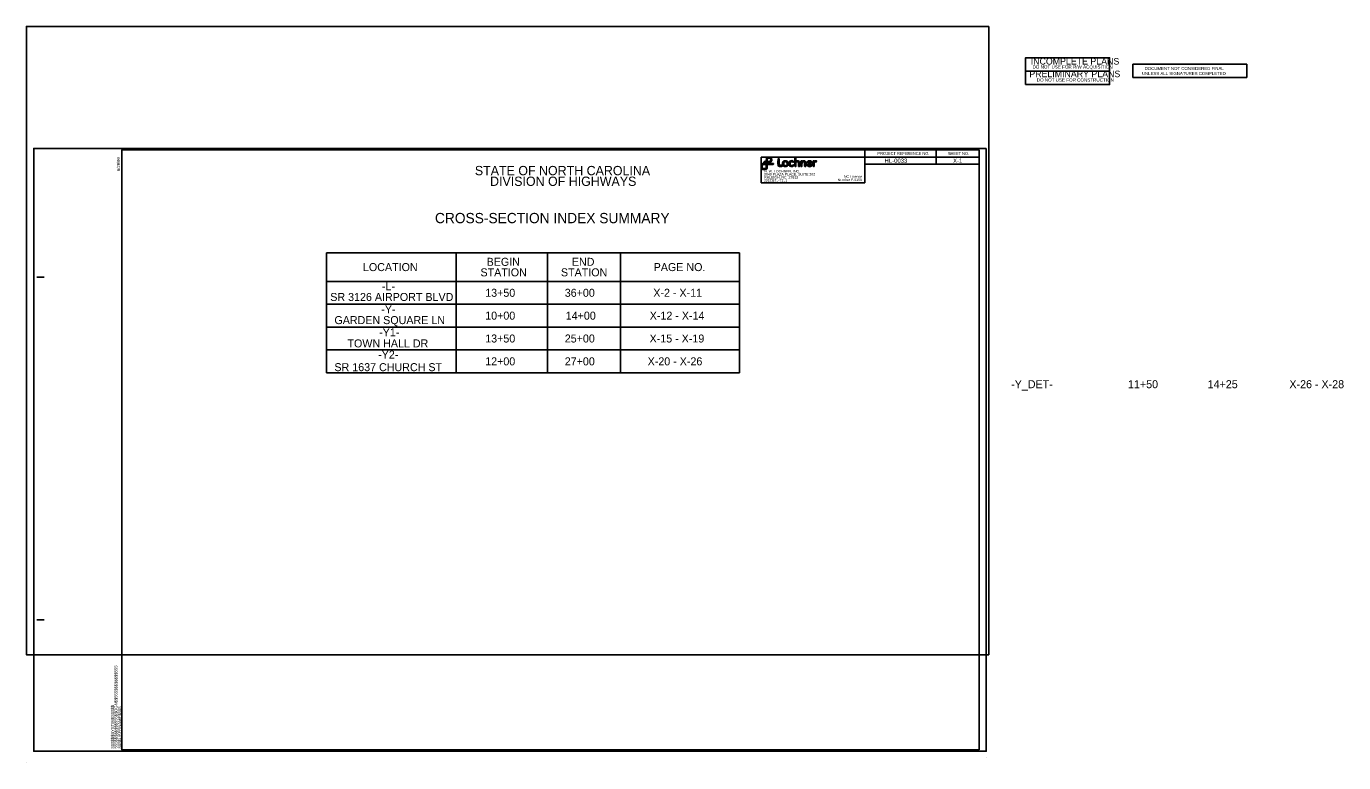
# Model space of a CAD drawing. Extents: x 1385764 to 1388069, y 199675 to 203361.
import ezdxf

# ---------------------------------------------------------------- set-up
doc = ezdxf.new("R2010")
doc.units = 0
for name, color, linetype in [('Old_Level_61', 7, 'Continuous'), ('Old_Level_62', 7, 'Continuous'), ('Prop XSC Text', 7, 'Continuous'), ('Sheet Data Field CELL', 7, 'Continuous'), ('Sheet Plan CELL', 7, 'Continuous'), ('Sheet Plot Border Inside CELL', 7, 'Continuous'), ('Sheet Plot Border Outside CELL', 7, 'Continuous'), ('Sheet Sticker Exception Certification CELL', 7, 'Continuous'), ('Sheet Sticker Incomplete CELL', 7, 'Continuous'), ('Sheet Sticker Preliminary CELL', 7, 'Continuous'), ('Sheet Summary CELL', 7, 'Continuous'), ('Sheet Summary Earthwork CELL', 7, 'Continuous')]:
    doc.layers.add(name, color=color, linetype=linetype)

msp = doc.modelspace()

# ---------------------------------------------------------------- linework, layer by layer
at = {"layer": 'Old_Level_61'}
for p, q in [((1387443.5, 203147.4), (1387443.5, 203147.4)), ((1385777.5, 202092.4), (1385777.5, 202092.4))]:
    msp.add_line(p, q, dxfattribs=at)
at = {"layer": 'Old_Level_62'}
for p, q in [((1387448, 203167.4), (1387448, 203167.4)), ((1385764.5, 202072.4), (1385764.5, 202072.4))]:
    msp.add_line(p, q, dxfattribs=at)
at = {"layer": 'Prop XSC Text'}
for p, q in [((1387049.6, 203132.3), (1387049.6, 203087.4)), ((1387230.9, 203132.3), (1387049.6, 203132.3)), ((1387230.9, 203132.3), (1387230.9, 203087.4)), ((1387230.9, 203087.4), (1387049.6, 203087.4)), ((1386288.9, 202964.8), (1387011.9, 202964.8)), ((1386288.9, 202964.8), (1386288.9, 202754.8)), ((1386516, 202964.8), (1386516, 202754.8)), ((1386676, 202964.8), (1386676, 202754.8)), ((1386803.7, 202964.8), (1386803.7, 202754.8)), ((1387011.9, 202964.8), (1387011.9, 202754.8)), ((1386288.9, 202914.8), (1387011.9, 202914.8)), ((1386288.9, 202874.8), (1387011.9, 202874.8)), ((1386288.9, 202834.8), (1387011.9, 202834.8)), ((1386288.9, 202794.8), (1387011.9, 202794.8)), ((1386288.9, 202754.8), (1387011.9, 202754.8))]:
    msp.add_line(p, q, dxfattribs=at)
for points in [[(1387058.6, 203121.3), (1387058.5, 203121.3), (1387058.4, 203121.3), (1387058.3, 203121.3), (1387057.2, 203121.3), (1387056.1, 203121.3), (1387055, 203121.3), (1387054.7, 203121.3), (1387054.3, 203121.2), (1387053.9, 203121.2), (1387051.1, 203120.7), (1387049.1, 203117.8), (1387049.6, 203115), (1387050.2, 203112.1), (1387052.7, 203110.2), (1387055.7, 203110.5), (1387058.3, 203110.8), (1387060.4, 203113.2), (1387060.4, 203115.8), (1387060.4, 203119.7), (1387060.4, 203123.6), (1387060.4, 203127.6), (1387060.4, 203129.5), (1387062.2, 203130.9), (1387064, 203130.4), (1387065.4, 203130.1), (1387066.4, 203128.8), (1387066.3, 203127.3), (1387066.1, 203125.9), (1387064.9, 203124.7), (1387063.4, 203124.6), (1387062.8, 203124.6), (1387062.2, 203124.6), (1387061.5, 203124.6), (1387061.4, 203124.6), (1387061.3, 203124.6), (1387061.2, 203124.6), (1387061.3, 203124), (1387061.4, 203123.5), (1387061.7, 203123), (1387061.8, 203123), (1387061.9, 203122.9), (1387062, 203122.9), (1387062.6, 203122.9), (1387063.2, 203122.9), (1387063.9, 203123), (1387066.5, 203123.2), (1387068.5, 203125.8), (1387067.9, 203128.6), (1387067.3, 203131.1), (1387065, 203132.6), (1387062.5, 203132.2), (1387060.5, 203131.9), (1387058.8, 203130), (1387058.7, 203128), (1387058.6, 203127), (1387058.6, 203126), (1387058.6, 203125), (1387058.6, 203124.9), (1387058.6, 203124.8), (1387058.6, 203124.6), (1387058.5, 203124.6), (1387058.4, 203124.6), (1387058.3, 203124.6), (1387057.6, 203124.6), (1387056.9, 203124.6), (1387056.2, 203124.6), (1387055.4, 203124.6), (1387054.8, 203124.2), (1387054.6, 203123.4), (1387054.5, 203123.3), (1387054.5, 203123.1), (1387054.5, 203122.9), (1387055.9, 203122.9), (1387057.3, 203122.9), (1387058.6, 203122.9), (1387058.6, 203122.3), (1387058.6, 203121.8), (1387058.6, 203121.3)], [(1387081.3, 203118.1), (1387081.3, 203122), (1387081.3, 203125.8), (1387081.3, 203129.6), (1387080.5, 203129.6), (1387079.8, 203129.6), (1387079.1, 203129.6), (1387079.1, 203125.1), (1387079.1, 203120.6), (1387079.1, 203116.1), (1387081.6, 203116.1), (1387084.1, 203116.1), (1387086.6, 203116.1), (1387086.6, 203116.7), (1387086.6, 203117.2), (1387086.6, 203117.8), (1387086.7, 203118), (1387086.6, 203118.1), (1387086.4, 203118.1), (1387084.8, 203118.1), (1387083.2, 203118.1), (1387081.6, 203118.1), (1387081.5, 203118.1), (1387081.4, 203118.1), (1387081.3, 203118.1)], [(1387115, 203116.1), (1387115.7, 203116.1), (1387116.4, 203116.1), (1387117, 203116.1), (1387117, 203116.2), (1387117.1, 203116.2), (1387117.1, 203116.3), (1387117.1, 203118.1), (1387117.1, 203120), (1387117, 203121.8), (1387117, 203122.2), (1387117, 203122.6), (1387116.9, 203123), (1387116.7, 203124.4), (1387115.9, 203125.4), (1387114.5, 203125.8), (1387113, 203126.2), (1387111.6, 203125.8), (1387110.6, 203124.6), (1387110.6, 203124.6), (1387110.5, 203124.5), (1387110.4, 203124.4), (1387110.4, 203124.6), (1387110.4, 203124.7), (1387110.4, 203124.8), (1387110.4, 203126.3), (1387110.4, 203127.9), (1387110.4, 203129.5), (1387110.4, 203129.7), (1387110.4, 203129.9), (1387110.3, 203130.1), (1387110, 203130.9), (1387109.1, 203131.4), (1387108.4, 203131.3), (1387108.4, 203126.2), (1387108.4, 203121.2), (1387108.4, 203116.1), (1387109, 203116.1), (1387109.7, 203116.1), (1387110.4, 203116.1), (1387110.4, 203116.2), (1387110.4, 203116.3), (1387110.4, 203116.4), (1387110.4, 203117.9), (1387110.4, 203119.4), (1387110.4, 203120.9), (1387110.4, 203121.2), (1387110.4, 203121.6), (1387110.5, 203122), (1387110.7, 203123.2), (1387111.5, 203123.9), (1387112.7, 203124.1), (1387113.8, 203124.2), (1387114.7, 203123.7), (1387114.9, 203122.5), (1387114.9, 203122.3), (1387115, 203122), (1387115, 203121.7), (1387115, 203120.6), (1387115, 203119.5), (1387115, 203118.3), (1387115, 203117.6), (1387115, 203116.9), (1387115, 203116.1)], [(1387058.6, 203119.5), (1387058.5, 203119.5), (1387058.4, 203119.5), (1387058.4, 203119.5), (1387057.2, 203119.5), (1387056.1, 203119.5), (1387054.9, 203119.5), (1387054.7, 203119.5), (1387054.5, 203119.5), (1387054.2, 203119.5), (1387052.3, 203119.1), (1387051, 203117.1), (1387051.3, 203115.2), (1387051.7, 203113.4), (1387053.2, 203112.2), (1387055.1, 203112.2), (1387056.9, 203112.3), (1387058.5, 203113.8), (1387058.6, 203115.6), (1387058.7, 203116.9), (1387058.6, 203118.1), (1387058.6, 203119.4), (1387058.6, 203119.4), (1387058.6, 203119.5), (1387058.6, 203119.5)], [(1387058.6, 203119.5), (1387058.6, 203119.5), (1387058.6, 203119.4), (1387058.6, 203119.4), (1387058.6, 203118.1), (1387058.7, 203116.9), (1387058.6, 203115.6), (1387058.5, 203113.8), (1387056.9, 203112.3), (1387055.1, 203112.2), (1387053.2, 203112.2), (1387051.7, 203113.4), (1387051.3, 203115.2), (1387051, 203117.1), (1387052.3, 203119.1), (1387054.2, 203119.5), (1387054.5, 203119.5), (1387054.7, 203119.5), (1387054.9, 203119.5), (1387056.1, 203119.5), (1387057.2, 203119.5), (1387058.4, 203119.5), (1387058.4, 203119.5), (1387058.5, 203119.5), (1387058.6, 203119.5)], [(1387058.6, 203119.5), (1387058.6, 203119.5), (1387058.6, 203119.4), (1387058.6, 203119.4), (1387058.6, 203118.1), (1387058.7, 203116.9), (1387058.6, 203115.6), (1387058.5, 203113.8), (1387056.9, 203112.3), (1387055.1, 203112.2), (1387053.2, 203112.2), (1387051.7, 203113.4), (1387051.3, 203115.2), (1387051, 203117.1), (1387052.3, 203119.1), (1387054.2, 203119.5), (1387054.5, 203119.5), (1387054.7, 203119.5), (1387054.9, 203119.5), (1387056.1, 203119.5), (1387057.2, 203119.5), (1387058.4, 203119.5), (1387058.4, 203119.5), (1387058.5, 203119.5), (1387058.6, 203119.5)], [(1387061.2, 203121.3), (1387061.3, 203120.7), (1387061.4, 203120.1), (1387061.8, 203119.7), (1387061.8, 203119.6), (1387062, 203119.5), (1387062.1, 203119.5), (1387064.7, 203119.5), (1387067.3, 203119.5), (1387069.9, 203119.5), (1387070.8, 203119.5), (1387071.6, 203120.4), (1387071.5, 203121.3), (1387068.1, 203121.3), (1387064.7, 203121.3), (1387061.2, 203121.3)], [(1387097.1, 203120.9), (1387097.1, 203123.8), (1387094.9, 203125.9), (1387092, 203125.9), (1387089.2, 203125.9), (1387087, 203123.8), (1387087, 203120.9), (1387087, 203118), (1387089.2, 203115.8), (1387092, 203115.8), (1387094.9, 203115.8), (1387097.1, 203118), (1387097.1, 203120.9)], [(1387089.1, 203120.7), (1387089.1, 203122), (1387089.5, 203122.9), (1387090.4, 203123.6), (1387091.8, 203124.6), (1387094.3, 203124.1), (1387094.9, 203121.8), (1387095.2, 203120.5), (1387095, 203119.4), (1387094, 203118.5), (1387092.4, 203116.9), (1387089.7, 203117.8), (1387089.2, 203120), (1387089.1, 203120.3), (1387089.1, 203120.6), (1387089.1, 203120.7)], [(1387106.9, 203124.2), (1387105.8, 203125.8), (1387103.5, 203126.4), (1387101.3, 203125.6), (1387099.2, 203124.9), (1387097.9, 203122.9), (1387098.1, 203120.5), (1387098.2, 203118.3), (1387099.7, 203116.5), (1387101.7, 203116), (1387103.9, 203115.5), (1387106, 203116.1), (1387107, 203117.6), (1387106.6, 203118), (1387106.2, 203118.5), (1387105.8, 203118.9), (1387105.6, 203118.8), (1387105.5, 203118.6), (1387105.3, 203118.5), (1387104.1, 203117.3), (1387101.9, 203117.4), (1387100.8, 203118.8), (1387100.3, 203119.5), (1387100.1, 203120.3), (1387100.2, 203121.2), (1387100.3, 203122.4), (1387101.1, 203123.5), (1387102.2, 203123.9), (1387103.4, 203124.3), (1387104.7, 203124), (1387105.5, 203123), (1387105.5, 203123), (1387105.6, 203122.9), (1387105.6, 203122.8), (1387106.1, 203123.3), (1387106.5, 203123.8), (1387106.9, 203124.2)], [(1387119.1, 203116.1), (1387119.8, 203116.1), (1387120.4, 203116.1), (1387121.1, 203116.1), (1387121.1, 203116.2), (1387121.1, 203116.3), (1387121.1, 203116.4), (1387121.1, 203117.9), (1387121.1, 203119.5), (1387121.1, 203121), (1387121.1, 203121.3), (1387121.2, 203121.6), (1387121.2, 203121.9), (1387121.4, 203123.1), (1387122.2, 203123.9), (1387123.4, 203124.1), (1387124.5, 203124.2), (1387125.4, 203123.8), (1387125.6, 203122.6), (1387125.7, 203122.3), (1387125.7, 203122.1), (1387125.7, 203121.8), (1387125.7, 203120), (1387125.7, 203118.2), (1387125.7, 203116.4), (1387125.7, 203116.3), (1387125.7, 203116.2), (1387125.7, 203116.1), (1387126.4, 203116.1), (1387127.1, 203116.1), (1387127.8, 203116.1), (1387127.8, 203116.2), (1387127.8, 203116.3), (1387127.8, 203116.4), (1387127.8, 203118.1), (1387127.8, 203119.8), (1387127.8, 203121.5), (1387127.8, 203121.9), (1387127.8, 203122.3), (1387127.7, 203122.6), (1387127.6, 203123.7), (1387127.2, 203124.6), (1387126.4, 203125.2), (1387125.8, 203125.7), (1387125.1, 203125.9), (1387124.4, 203125.9), (1387123.1, 203126), (1387122, 203125.6), (1387121.2, 203124.6), (1387121.2, 203124.5), (1387121.1, 203124.5), (1387121.1, 203124.4), (1387121.1, 203124.9), (1387121.1, 203125.2), (1387121.1, 203125.6), (1387120.4, 203125.6), (1387119.7, 203125.6), (1387119.1, 203125.6), (1387119.1, 203122.5), (1387119.1, 203119.3), (1387119.1, 203116.1)], [(1387138.8, 203120.2), (1387138.8, 203120.5), (1387138.8, 203120.8), (1387138.8, 203121.2), (1387138.7, 203122.1), (1387138.5, 203123), (1387138, 203123.8), (1387137, 203125.4), (1387135.5, 203126), (1387133.7, 203125.9), (1387131.7, 203125.8), (1387130.4, 203124.7), (1387129.7, 203122.9), (1387129.2, 203121.6), (1387129.2, 203120.3), (1387129.6, 203119), (1387129.9, 203118.1), (1387130.5, 203117.4), (1387131.3, 203116.8), (1387133, 203115.5), (1387135.9, 203115.5), (1387137.7, 203116.8), (1387138, 203117.1), (1387138.3, 203117.4), (1387138.6, 203117.6), (1387138.2, 203118.1), (1387137.8, 203118.5), (1387137.4, 203118.9), (1387137.3, 203118.9), (1387137.2, 203118.8), (1387137.2, 203118.7), (1387136.3, 203118), (1387135.3, 203117.6), (1387134.2, 203117.7), (1387133.2, 203117.8), (1387132.4, 203118.1), (1387131.9, 203118.9), (1387131.6, 203119.3), (1387131.5, 203119.7), (1387131.5, 203120.2), (1387132.7, 203120.2), (1387133.9, 203120.2), (1387135.1, 203120.2), (1387136.3, 203120.2), (1387137.5, 203120.2), (1387138.8, 203120.2)], [(1387136.6, 203121.9), (1387134.9, 203121.9), (1387133.2, 203121.9), (1387131.5, 203121.9), (1387131.4, 203122.8), (1387132.6, 203124), (1387133.8, 203124), (1387135.4, 203124.2), (1387136.6, 203123.2), (1387136.6, 203121.9)], [(1387146.5, 203125.5), (1387146.5, 203125.5), (1387146.5, 203125.6), (1387146.5, 203125.6), (1387146.4, 203125.6), (1387146.4, 203125.6), (1387146.3, 203125.6), (1387144.8, 203126), (1387143.5, 203125.7), (1387142.4, 203124.5), (1387142.4, 203124.5), (1387142.4, 203124.5), (1387142.3, 203124.4), (1387142.3, 203124.9), (1387142.3, 203125.3), (1387142.3, 203125.6), (1387141.6, 203125.6), (1387141, 203125.6), (1387140.4, 203125.6), (1387140.4, 203122.4), (1387140.4, 203119.3), (1387140.4, 203116.1), (1387141.1, 203116.1), (1387141.7, 203116.1), (1387142.4, 203116.1), (1387142.4, 203116.2), (1387142.4, 203116.3), (1387142.4, 203116.4), (1387142.4, 203118), (1387142.4, 203119.7), (1387142.4, 203121.3), (1387142.5, 203122.6), (1387143.3, 203123.6), (1387144.6, 203123.8), (1387145.1, 203123.9), (1387145.5, 203123.8), (1387146, 203123.6), (1387146, 203123.7), (1387146, 203123.8), (1387146.1, 203123.9), (1387146.2, 203124.4), (1387146.3, 203125), (1387146.5, 203125.5)]]:
    msp.add_open_spline(points, degree=3, dxfattribs=at)
at = {"layer": 'Sheet Plan CELL'}
for p, q in [((1385782.4, 202922.3), (1385795, 202922.4)), ((1385782.5, 202322.4), (1385795, 202322.3))]:
    msp.add_line(p, q, dxfattribs=at)
at = {"layer": 'Sheet Plot Border Inside CELL'}
msp.add_lwpolyline([(1387443.5, 203147.4), (1385777, 203147.4), (1385777, 202092.3), (1387443.5, 202092.3)], close=True, dxfattribs=at)
at = {"layer": 'Sheet Plot Border Outside CELL'}
msp.add_lwpolyline([(1387448, 203361.2), (1385764, 203361.2), (1385764, 202261.2), (1387448, 202261.2)], close=True, dxfattribs=at)
at = {"layer": 'Sheet Sticker Exception Certification CELL'}
for p, q in [((1387699.7, 203271.5), (1387699.7, 203295)), ((1387699.7, 203295), (1387899.7, 203295)), ((1387899.7, 203295), (1387899.7, 203271.5)), ((1387899.7, 203271.5), (1387699.7, 203271.5))]:
    msp.add_line(p, q, dxfattribs=at)
at = {"layer": 'Sheet Sticker Incomplete CELL'}
msp.add_lwpolyline([(1387512.3, 203282.6), (1387512.3, 203306.1), (1387659.3, 203306.1), (1387659.3, 203282.6)], close=True, dxfattribs=at)
at = {"layer": 'Sheet Sticker Preliminary CELL'}
msp.add_lwpolyline([(1387512.3, 203259.1), (1387512.3, 203282.6), (1387659.3, 203282.6), (1387659.3, 203259.1)], close=True, dxfattribs=at)
at = {"layer": 'Sheet Summary CELL'}
for p, q in [((1385931, 203144.9), (1385931, 203104.4)), ((1387230.9, 203132.3), (1387431, 203132.3)), ((1387356, 203144.8), (1387356, 203119.8)), ((1387230.9, 203119.8), (1387431, 203119.8)), ((1385782.5, 202922.4), (1385795, 202922.4)), ((1385782.5, 202322.4), (1385795, 202322.4)), ((1385931, 202094.9), (1385931, 202094.9)), ((1385931, 202094.9), (1385931, 202094.9)), ((1385931, 202094.9), (1385931, 202094.9)), ((1385931, 202094.9), (1385931, 202094.9)), ((1385931, 202094.9), (1385931, 202094.9)), ((1385931, 202094.9), (1385931, 202094.9))]:
    msp.add_line(p, q, dxfattribs=at)
for points in [[(1387431, 203144.9), (1385931, 203144.9), (1385931, 202094.9), (1387431, 202094.9)], [(1387230.9, 203144.9), (1387431, 203144.9), (1387431, 203119.8), (1387230.9, 203119.8)]]:
    msp.add_lwpolyline(points, close=True, dxfattribs=at)
at = {"layer": 'Sheet Summary Earthwork CELL'}
for p, q in [((1385763.9, 203157.6), (1385763.9, 203157.6)), ((1387444.2, 202082.1), (1387444.2, 202082.1))]:
    msp.add_line(p, q, dxfattribs=at)

# ---------------------------------------------------------------- texts
at = {"layer": 'Prop XSC Text'}
for s, height, p in [('H. W. LOCHNER, INC.', 4.423, (1387055.1, 203105.4)), ('2840 PLAZA PLACE, SUITE 202', 4.423, (1387054.6, 203100.1)), ('(919)571-7111', 4.423, (1387055.1, 203089.3)), ('RALEIGH, NC  27612', 4.423, (1387055.1, 203094.7)), ('Number F-0159', 4.423, (1387183.4, 203090.3)), ('NC License', 4.42, (1387194.7, 203096.1))]:
    msp.add_text(s, height=height, rotation=360, dxfattribs=at).set_placement(p)
for s, height, p in [('CROSS-SECTION INDEX SUMMARY', 18, (1386478.9, 203016.6)), ('LOCATION', 14, (1386352.9, 202932.8)), ('BEGIN', 14, (1386569.3, 202942)), ('END', 14, (1386718.4, 202942)), ('PAGE NO.', 14, (1386861.6, 202932.8)), ('STATION', 14, (1386558.5, 202923.6)), ('STATION', 14, (1386699.3, 202923.6)), ('-L-', 14, (1386386.1, 202899.3)), ('13+50', 14, (1386566.8, 202887.8)), ('36+00', 14, (1386706, 202887.8)), ('X-2 - X-11', 14, (1386860.9, 202887.8)), ('SR 3126 AIRPORT BLVD', 14, (1386295.7, 202880.5)), ('GARDEN SQUARE LN', 14, (1386303, 202840)), ('-Y-', 14, (1386385, 202859.1)), ('10+00', 14, (1386566.8, 202847.8)), ('14+00', 14, (1386707.7, 202847.8)), ('X-12 - X-14', 14, (1386854.7, 202847.8)), ('-Y1-', 14, (1386381.2, 202818.6)), ('TOWN HALL DR', 14, (1386325.8, 202799.2)), ('13+50', 14, (1386566.8, 202807.8)), ('25+00', 14, (1386706, 202807.8)), ('X-15 - X-19', 14, (1386854.4, 202807.8)), ('-Y2-', 14, (1386379.5, 202779.6)), ('SR 1637 CHURCH ST', 14, (1386303, 202757.6)), ('12+00', 14, (1386566.8, 202767.8)), ('27+00', 14, (1386706, 202767.8)), ('X-20 - X-26', 14, (1386851, 202767.8)), ('-Y_DET-', 14, (1387487.1, 202727.8)), ('11+50', 14, (1387691.5, 202727.8)), ('14+25', 14, (1387830.9, 202727.8)), ('X-26 - X-28', 14, (1387973.9, 202727.8))]:
    msp.add_text(s, height=height, dxfattribs=at).set_placement(p)
at = {"layer": 'Sheet Data Field CELL'}
for s, p in [('HL-0033', (1387265.6, 203122.3)), ('X-1', (1387385.5, 203122.3))]:
    msp.add_text(s, height=7.5, dxfattribs=at).set_placement(p)
at = {"layer": 'Sheet Sticker Exception Certification CELL'}
for s, p in [('UNLESS ALL SIGNATURES COMPLETED', (1387715.7, 203275.9)), ('DOCUMENT NOT CONSIDERED FINAL', (1387720.7, 203284.7))]:
    msp.add_text(s, height=5.5, dxfattribs=at).set_placement(p)
at = {"layer": 'Sheet Sticker Incomplete CELL'}
for s, height, p in [('INCOMPLETE PLANS', 11.52, (1387521.3, 203294.3)), ('DO NOT USE FOR R/W ACQUISITION', 5.76, (1387524.5, 203287.3))]:
    msp.add_text(s, height=height, rotation=359.9964, dxfattribs=at).set_placement(p)
at = {"layer": 'Sheet Sticker Preliminary CELL'}
for s, height, p in [('PRELIMINARY PLANS', 11.52, (1387518.8, 203272.2)), ('DO NOT USE FOR CONSTRUCTION', 5.76, (1387531.9, 203264.5))]:
    msp.add_text(s, height=height, dxfattribs=at).set_placement(p)
at = {"layer": 'Sheet Summary CELL'}
for s, p in [('5/28/99', (1385927.7, 203107.8)), ('$$$$$$$$$$$$$$$$DGN$$$$$$$$$$$$$$$$', (1385923.3, 202097.2)), ('$$$$$$SYSTIME$$$$$', (1385917.3, 202097.2)), ('$$$$USERNAME$$$$', (1385929.9, 202097.2))]:
    msp.add_text(s, height=5.25, rotation=90, dxfattribs=at).set_placement(p)
for s, height, p in [('PROJECT REFERENCE NO.', 5, (1387253.1, 203136.2)), ('SHEET NO.', 5, (1387376.3, 203136.1)), ('STATE OF NORTH CAROLINA', 16.25, (1386548.7, 203100.6)), ('DIVISION OF HIGHWAYS', 16.25, (1386575.3, 203081.9))]:
    msp.add_text(s, height=height, dxfattribs=at).set_placement(p)

doc.saveas('drawing.dxf')
